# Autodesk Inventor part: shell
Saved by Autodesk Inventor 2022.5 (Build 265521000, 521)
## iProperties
Created: 2024-12
Part Number: shell
Material: Generic
Document SubType Name: Modeling
Designer: AdminForWorker
Density: 1 g/cm^3
Appearance: Default
Title: shell
Author: AdminForWorker
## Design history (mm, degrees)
feature "Body2"
body "Solid1"
